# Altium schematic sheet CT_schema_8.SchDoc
size 274 x 160 mm
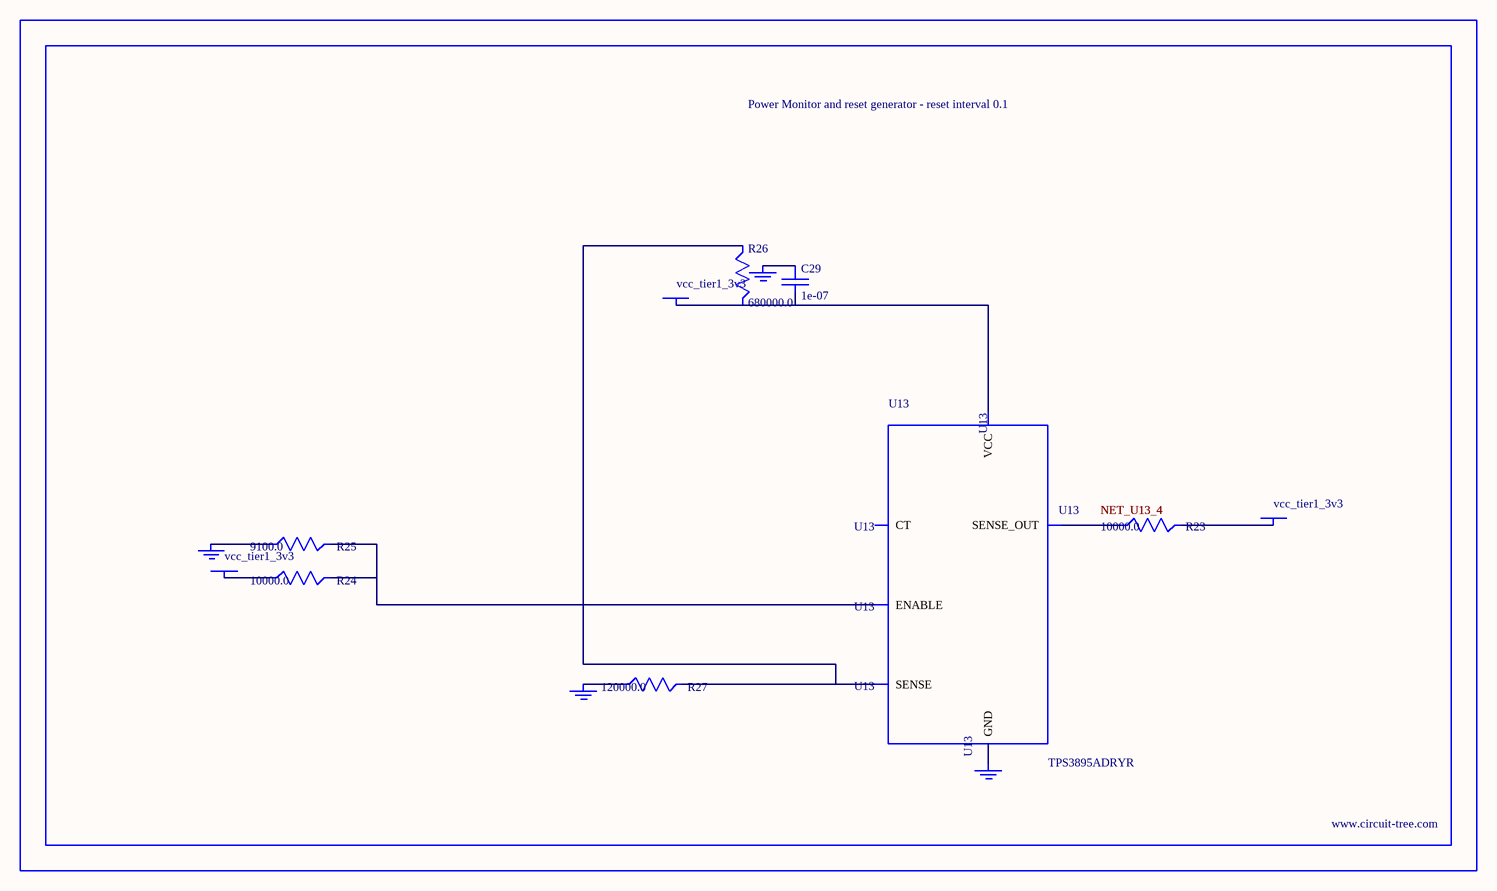
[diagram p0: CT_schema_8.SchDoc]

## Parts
BORDER7  (no value)
C29  1e-07  [C0402]
GND_INSTANCE_7_0  (no value)
GND_INSTANCE_7_1  (no value)
GND_INSTANCE_7_2  (no value)
GND_INSTANCE_7_3  (no value)
POWER_INSTANCE_7_0  vcc_tier1_3v3
POWER_INSTANCE_7_1  vcc_tier1_3v3
POWER_INSTANCE_7_2  vcc_tier1_3v3
R23  10000.0  [R0603]
R24  10000.0  [R0603]
R25  9100.0  [R0603]
R26  680000.0  [R0603]
R27  120000.0  [R0603]
U13  TPS3895ADRYR  [SON-6]

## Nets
NetC29_1: C29.1 GND_INSTANCE_7_2.0(GND)
NetC29_2: C29.2 POWER_INSTANCE_7_2.0(PWR) R26.2 U13.6(VCC)
NetGND_INSTANCE_7_0_0: GND_INSTANCE_7_0.0(GND) R25.1
NetGND_INSTANCE_7_1_0: GND_INSTANCE_7_1.0(GND) R27.1
NetGND_INSTANCE_7_3_0: GND_INSTANCE_7_3.0(GND) U13.2(GND)
NetPOWER_INSTANCE_7_0_0: POWER_INSTANCE_7_0.0(PWR) R24.1
NetPOWER_INSTANCE_7_1_0: POWER_INSTANCE_7_1.0(PWR) R23.2
NetR23_1: R23.1 U13.4(SENSE_OUT)
NetR24_2: R24.2 R25.2 U13.1(ENABLE)
NetR26_1: R26.1 R27.2 U13.3(SENSE)

Not connected (* = marked no-connect by the designer): U13 5(CT)

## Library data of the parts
BORDER7 = BORDER_PAGE7
C29 = C0402C104K3RACTU
GND_INSTANCE_7_0-GND_INSTANCE_7_3 = GND
POWER_INSTANCE_7_0-POWER_INSTANCE_7_2 = PWR
R23 R24 = RC0603JR-0710KL
R25 = RC0603JR-079K1L
R26 = RC0603JR-07680KL
R27 = RC0603JR-07120KL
